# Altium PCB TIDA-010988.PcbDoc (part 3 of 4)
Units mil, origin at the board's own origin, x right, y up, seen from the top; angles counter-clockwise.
Board outline 3937.01 x 2559.06 mil, 4 copper layers (Top Layer, GND1, GND2, Bottom Layer), stack 61.6 mil thick; 270 components, 141 nets, 796 pads, 474 vias.
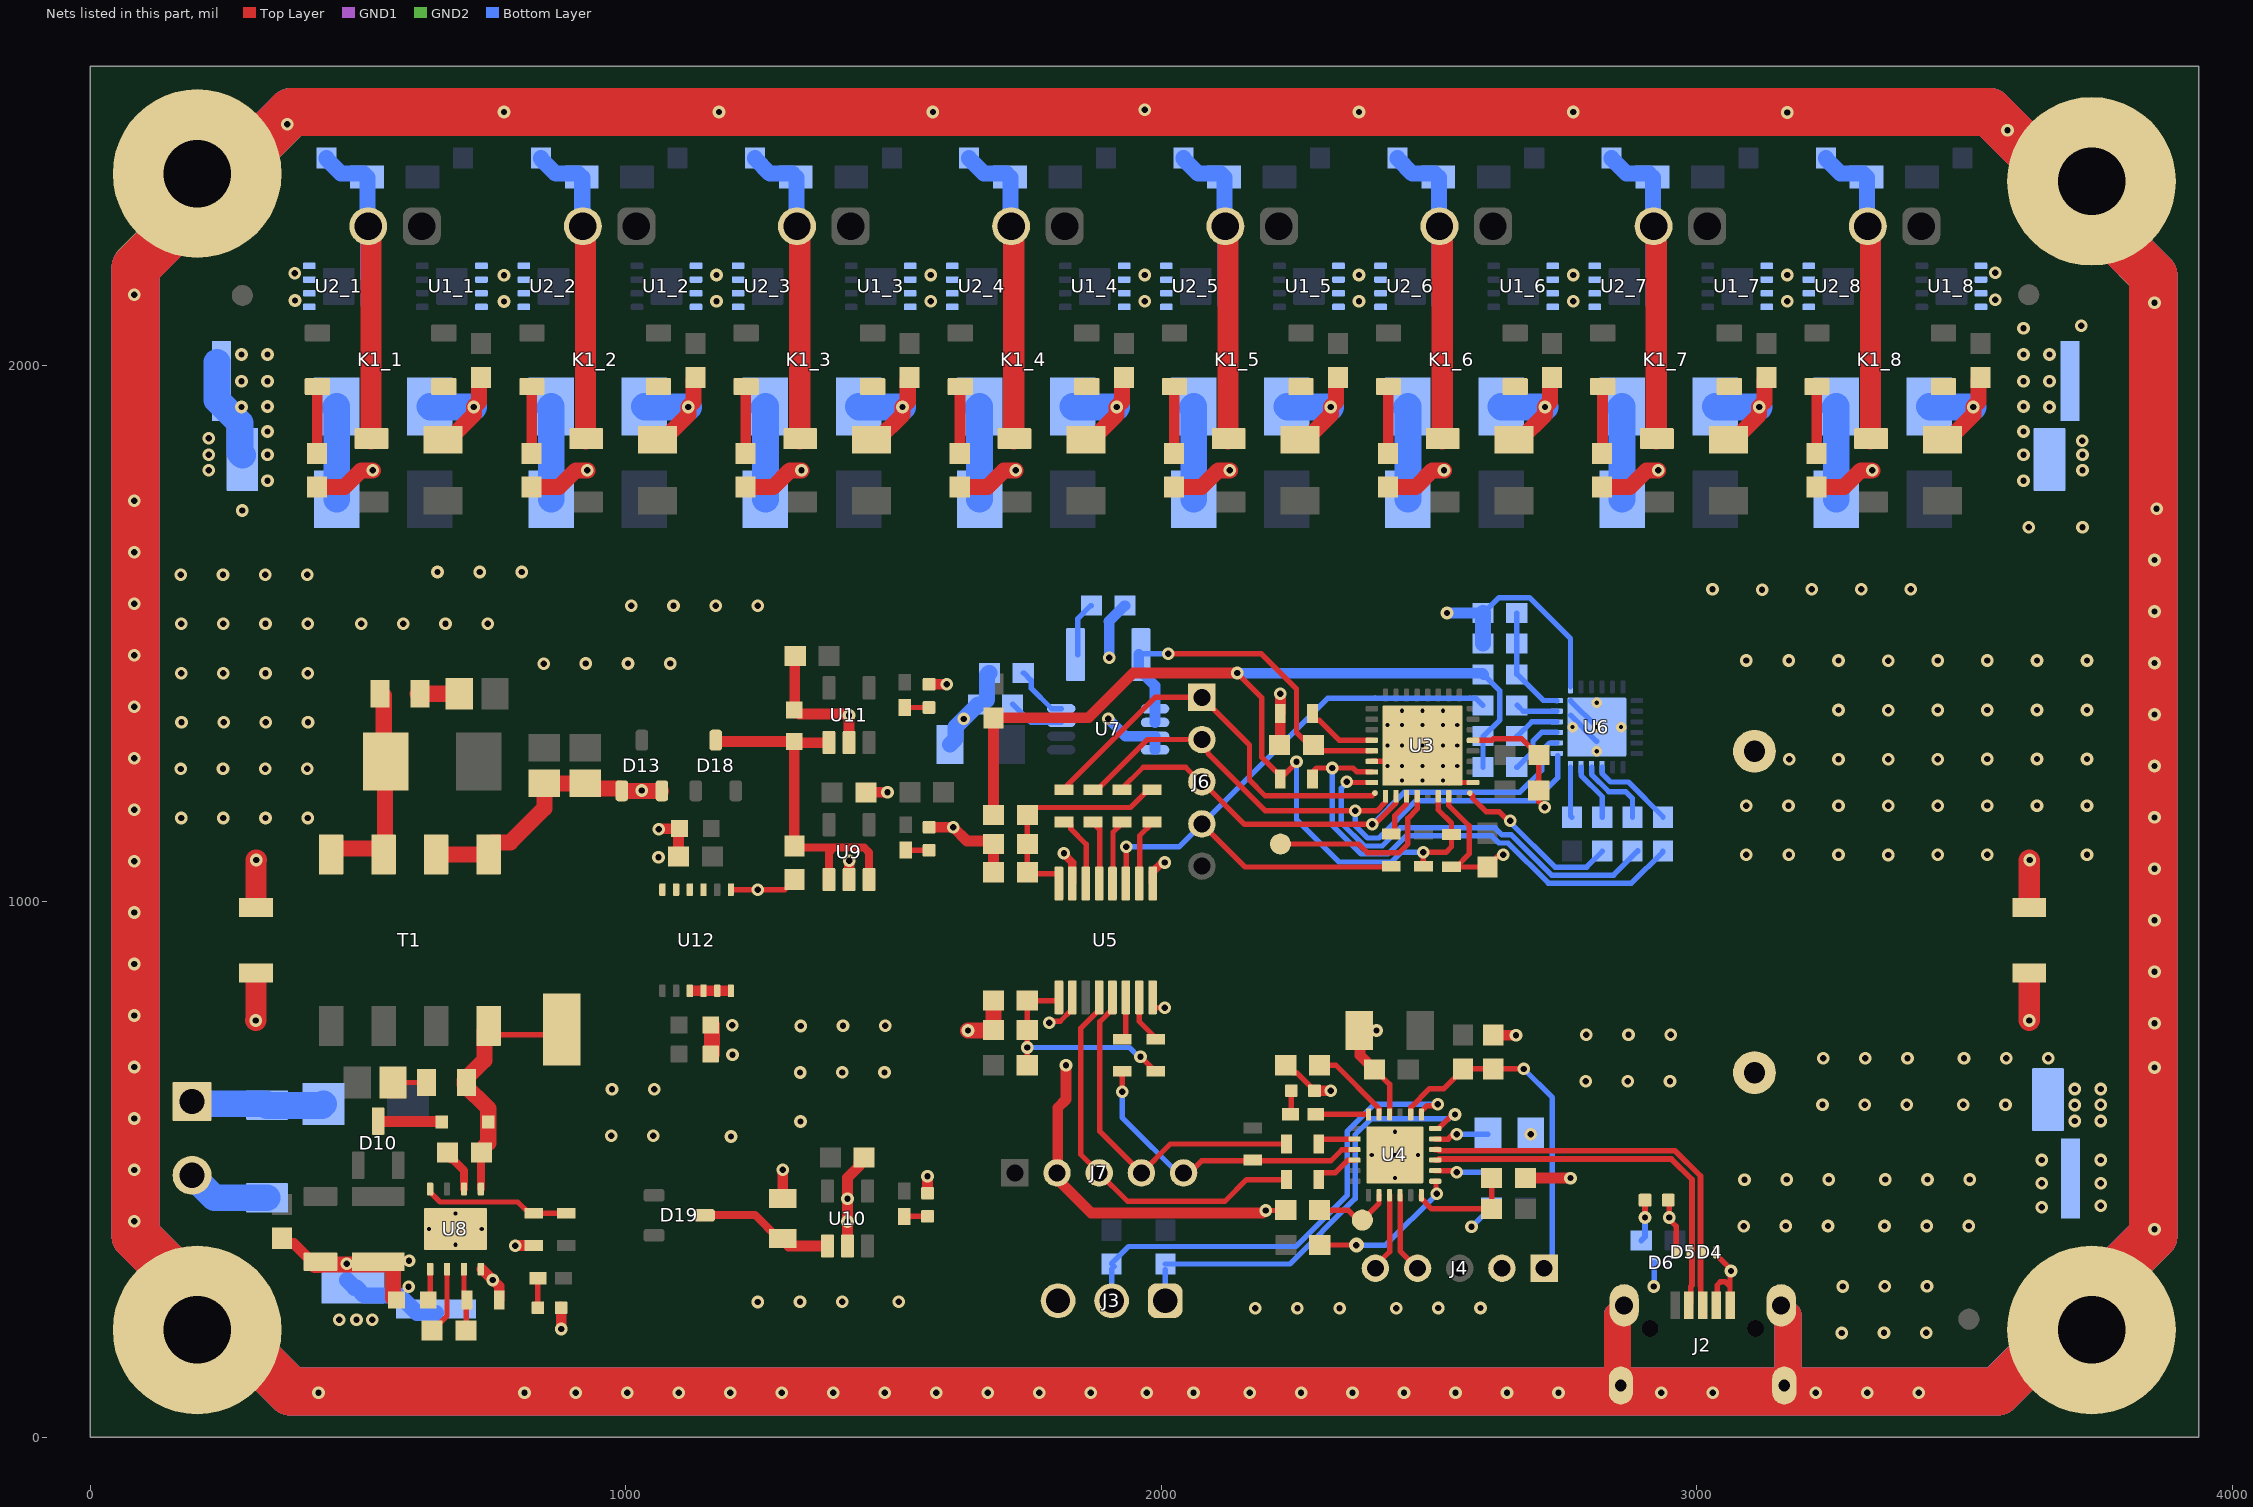
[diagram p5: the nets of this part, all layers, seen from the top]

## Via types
v1: diameter 23.62, hole 11.81, Top Layer to Bottom Layer, tented both sides, 374 vias
v2: diameter 19.68, hole 7.87, Top Layer to Bottom Layer, tented top, 64 vias
v3: diameter 19.68, hole 7.87, Top Layer to Bottom Layer, tented both sides, 26 vias
v4: diameter 19.68, hole 7.87, Top Layer to Bottom Layer, 9 vias
v5: diameter 28, hole 12, Top Layer to Bottom Layer, tented both sides, 1 vias

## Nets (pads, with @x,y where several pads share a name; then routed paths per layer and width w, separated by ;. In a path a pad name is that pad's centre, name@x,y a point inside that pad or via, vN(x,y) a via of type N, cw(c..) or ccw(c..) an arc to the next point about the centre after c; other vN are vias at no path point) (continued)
E_GND: C1_1.2 C1_2.2 C1_3.2 C1_4.2 C1_5.2 C1_6.2 C1_7.2 C1_8.2 C2_1.1 C2_2.1 C2_3.1 C2_4.1 C2_5.1 C2_6.1 C2_7.1 C2_8.1 C24.1 C25.2 C45.1 C46.2 H1.1 H2.1 H3.1 H4.1 J2.Z1 J2.Z2 J2.Z3 J2.Z4 R1_1.1 R1_2.1 R1_3.1 R1_4.1 R1_5.1 R1_6.1 R1_7.1 R1_8.1 R2_1.2 R2_2.2 R2_3.2 R2_4.2 R2_5.2 R2_6.2 R2_7.2 R2_8.2 R36.2 R37.2 R39.2 R40.2 | length 47388
  Top Layer w50: J2.Z4@2851.63,110.96 J2.Z1@2851.63,227.74 ; J2.Z3@3169.98,110.96 J2.Z2@3169.98,227.74
  Top Layer w90: H3.1@260.87,200 H3.1@259.08,200 ; 374.07,2473.16 374.98,2473.16 ; v1@2739.82,85 2164.98,85 1972.77,85 1483.71,85 1003.18,85 810.97,85 374.08,85 H3.1@259.08,200 ; v1@2741.61,85 2858.25,85 3222.14,85 3561.36,85 3676.36,200 H4.1@3737.01,200 3737.01,260.87 3852.01,375.87 ; v1@3852.01,388.04 3852.01,964.67 3852.01,1060.78 3852.01,1252.99 3852.01,1349.09 3852.01,1733.51 3852.01,2117.94 3852.01,2163.11 ; 3852.01,2168.61 3737.01,2283.61 H2.1@3737.01,2344.49 3676.13,2344.49 3546.57,2474.06 v1(2769.12,2474.06) v1(2369.26,2474.06) v1(1573.68,2474.06) v1(1174.17,2474.06) v1(772.81,2474.06) 375.87,2474.06 374.98,2473.16 ; H3.1@259.08,200 H3.1@200,200 200,260.87 85,375.87 85,594.82 85,690.92 85,1267.56 85,1651.98 85,2132.51 85,2183.18 200,2298.18 H1.1@200,2359.06 260.87,2359.06 374.98,2473.16
  GND1 w50: J2.Z4@2851.63,110.96 J2.Z1@2851.63,227.74 ; J2.Z3@3169.98,110.96 J2.Z2@3169.98,227.74
  GND1 w90: H3.1@200,260.87 85,375.87 85,402.61 85,690.92 85,979.24 85,1267.56 85,1651.98 85,2183.18 200,2298.18 H1.1@200,2359.06 ; H1.1@259.07,2358.16 374.07,2473.16 ; H3.1@259.08,200 374.08,85 ; 375.87,85 1003.18,85 1483.71,85 1972.77,85 2261.09,85 2357.19,85 2858.25,85 3318.25,85 3561.13,85 H4.1@3676.13,200 ; 375.87,2474.06 v1(772.81,2474.06) v1(1174.17,2474.06) v1(1573.68,2474.06) v1(2369.26,2474.06) v1(2769.12,2474.06) 3546.57,2474.06 H2.1@3676.13,2344.49 ; H4.1@3735.2,259.98 3850.2,374.98 ; H2.1@3737.01,2283.61 3852.01,2168.61 3852.01,1829.62 3852.01,1733.51 3852.01,1541.31 3852.01,1252.99 3852.01,964.67 3852.01,690 3852.01,375.87
  GND2 w50: J2.Z4@2851.63,110.96 J2.Z1@2851.63,227.74 ; J2.Z3@3169.98,110.96 J2.Z2@3169.98,227.74
  GND2 w90: 85,2183.18 85,1651.98 85,1555.87 85,979.24 85,787.03 85,375.87 H3.1@200,260.87 ; 86.64,2187.45 H1.1@201.64,2302.45 ; H3.1@200,200 259.08,200 374.08,85 810.97,85 1003.18,85 1483.71,85 1675.92,85 2164.98,85 2645.51,85 3029.93,85 3169.98,85 3561.13,85 ; H1.1@200,2359.06 260.87,2359.06 375.87,2474.06 v1(772.81,2474.06) v1(1174.17,2474.06) v1(1573.68,2474.06) v1(2369.26,2474.06) v1(2769.12,2474.06) 3546.57,2474.06 H2.1@3676.13,2344.49 ; 3561.36,85 H4.1@3676.36,200 ; H4.1@3737.01,200 3737.01,260.87 3852.01,375.87 3852.01,690 3852.01,1349.09 3852.01,1541.31 3852.01,1637.41 3852.01,1733.51 3852.01,1829.62 3852.01,2168.13 3823.14,2197 3823.14,2197.48 3737.01,2283.61 H2.1@3737.01,2344.49
  Bottom Layer w50: J2.Z4@2858.25,96.28 2858.25,104.35 2851.63,110.96 2851.63,227.74 2864.15,240.26 J2.Z1@2864.15,245.88 ; J2.Z2@3157.46,245.88 3157.46,240.26 3169.98,227.74 3169.98,110.96 3163.36,104.35 J2.Z3@3163.36,96.28
  Bottom Layer w90: H3.1@260.87,200 H3.1@259.08,200 ; 374.08,85 H3.1@259.08,200 ; 375.87,85 426.55,85 1003.18,85 1483.71,85 1868.13,85 2645.51,85 2933.82,85 3163.36,85 3561.13,85 3676.13,200 H4.1@3737.01,200 3737.01,260.87 3852.01,375.87 3852.01,388.04 3852.01,482.36 3852.01,610.46 3852.01,676.36 3852.01,868.57 3852.01,1252.99 3852.01,1445.2 3852.01,1733.51 3852.01,1833.15 3852.01,2168.61 3737.01,2283.61 H2.1@3737.01,2344.49 3676.13,2344.49 3546.57,2474.06 3420.38,2474.06 3240.85,2474.06 3096.29,2474.06 v1(2769.12,2474.06) 2696.43,2474.06 2441.13,2474.06 v1(2369.26,2474.06) 1896.71,2474.06 1717.51,2474.06 v1(1573.68,2474.06) 1421.07,2474.06 v1(1174.17,2474.06) v1(772.81,2474.06) 517.16,2474.06 375.87,2474.06 260.87,2359.06 H1.1@200,2359.06 200,2298.18 85,2183.18 85,1833.15 85,1459.77 85,690.92 85,594.82 85,375.87 200,260.87 H3.1@200,200 H3.1@259.08,200
  other v1: 426.55,82.52 810.97,82.52 907.08,82.52 1003.18,82.52 1099.29,82.52 1195.39,82.52 1291.5,82.52 1387.61,82.52 1483.71,82.52 1579.82,82.52 1675.92,82.52 1772.03,82.52 1868.13,82.52 1972.77,82.52 2060.34,82.52 2164.98,82.52 2261.09,82.52 2357.19,82.52 2453.3,82.52 2549.4,82.52 2645.51,82.52 2741.61,82.52 2933.82,82.52 3029.93,82.52 3222.14,82.52 3318.25,82.52 3414.35,82.52 3854.49,388.04 82.52,402.61 82.52,498.71 82.52,594.82 82.52,690.92 3854.49,690 3854.49,772.46 82.52,787.03 3854.49,868.57 82.52,883.13 3854.49,964.67 82.52,979.24 3854.49,1060.78 82.52,1075.34 3854.49,1156.88 82.52,1171.45 3854.49,1252.99 82.52,1267.56 3854.49,1349.09 82.52,1363.66 3854.49,1445.2 82.52,1459.77 3854.49,1541.31 82.52,1555.87 3854.49,1637.41 82.52,1651.98 3858.42,1733.51 82.52,1748.08 3854.49,2117.94 82.52,2132.51 3580,2440 368.18,2450.9 3168.98,2473.16 1969.39,2478.33
F\A\U\L\T\: R9.2 U6.11 | length 110.1
  Bottom Layer w10: U6.11@2783.68,1250.78 2783.96,1250.51 2783.96,1235.47 2823.4,1196.02 R9.2@2823.4,1157.18
GND: C3.2 C4.2 C5.2 C6.2 C7.2 C8.2 C11.2 C12.2 C13.2 C14.2 C18.1 C20.2 C22.2 C23.2 C25.1 C28.2 C29.2 C30.2 C35.2 C36.2 C40.2 C43.1 C44.2 C46.1 D13.1 D13.2 D17.1 D21.1 R3_1.1 R3_2.1 R3_3.1 R3_4.1 R3_5.1 R3_6.1 R3_7.1 R3_8.1 R33.1 R35.1 R37.1 R40.1 T1.7 T1.8 TP1.1 U1_1.5 U1_1.6 U1_1.7 U1_1.8 U1_2.5 U1_2.6 U1_2.7 U1_2.8 U1_3.5 U1_3.6 U1_3.7 U1_3.8 U1_4.5 U1_4.6 U1_4.7 U1_4.8 U1_5.5 U1_5.6 U1_5.7 U1_5.8 U1_6.5 U1_6.6 U1_6.7 U1_6.8 U1_7.5 U1_7.6 U1_7.7 U1_7.8 U1_8.5 U1_8.6 U1_8.7 U1_8.8 U2_1.5 U2_1.6 U2_1.7 U2_1.8 U2_2.5 U2_2.6 U2_2.7 U2_2.8 U2_3.5 U2_3.6 U2_3.7 U2_3.8 U2_4.5 U2_4.6 U2_4.7 U2_4.8 U2_5.5 U2_5.6 U2_5.7 U2_5.8 U2_6.5 U2_6.6 U2_6.7 U2_6.8 U2_7.5 U2_7.6 U2_7.7 U2_7.8 U2_8.5 U2_8.6 U2_8.7 U2_8.8 U3.15 U3.25 U3.28 U3.32 U3.37 U5.9 U5.15 U6.19 U6.25 U7.7 U7.8 U9.2 U11.2 U12.7 U12.9 U12.10 U12.11 U12.12 | length 4400.4
  Top Layer w10: U12.7@1196.56,1022.04 1297.12,1022.04 C35.2@1314.86,1039.77 ; U3.15@2393.15,1261.5 2417.83,1261.5 2422.68,1256.66 v3(2422.68,1252.64) ; U3.37@2497.48,1300.87 v3(2487.64,1291.03) v3(2526.02,1252.64) 2556.46,1222.21 2582.05,1222.21 U3.28@2582.13,1222.13 ; v3(2526.02,1226.07) 2532.01,1226.07 U3.37@2536.85,1221.23 ; U3.25@2536.85,1196.54 2536.85,1179.31 2574.9,1141.27 2574.9,1088.51 2551.7,1065.31 2551.7,1064.33 C4.2@2609.12,1064.33 2609.12,1065.31 2628.58,1084.78 2636.05,1084.78 v1(2638.66,1087.38) ; U3.32@2582.13,1300.87 2617.26,1300.87 2619.9,1303.52 2673.56,1303.52 2704,1273.08 C8.2@2704.98,1273.08 2704.98,1207.19 C3.2@2704.92,1207.13 2704.92,1186.28 2705.42,1186.28 v1(2716.04,1175.65)
  Top Layer w15: v1@1818.27,1088.52 1833.82,1072.97 1833.82,1034.55 U5.15@1833.96,1034.41 ; U5.9@1983.96,1034.41 1983.96,1054.88 2001.85,1072.77 v1(2006.7,1072.77)
  Top Layer w20: v1(1061.93,1134.98) 1062.55,1135.6 1098.14,1135.6 1098.76,1136.23 C44.2@1098.76,1083.52 ; C40.2@1315.74,1457.11 1315.74,1360.42 1314.86,1359.54 1314.86,1358.74 1323.56,1350.04 1413.85,1350.04 1416.08,1347.81 v1(1417.06,1347.81) ; U11.2@1417.01,1296.55 v1@1417.01,1346.54 ; U9.2@1417.43,1041.17 v1@1417.43,1075.78 ; C36.2@1448.51,1203.81 v1@1488.95,1203.78 ; D17.1@1566.44,1138.59 v1@1611.44,1138.59 ; D21.1@1566.44,1405.35 1566.82,1405.73 v1@1596.69,1405.73 ; v1(1611.47,1138.56) 1637.29,1112.73 1681.46,1112.73 C12.2@1686.98,1107.22 C11.2@1686.98,1054.5 ; C5.2@2222.41,1291.69 C5.2@2222.41,1305.03 ; C5.2@2222.43,1305.05 C6.2@2222.41,1350.91 ; C6.2@2222.62,1351.12 v1@2222.62,1385.95
  Top Layer w30: R3_1.1@423.44,1773.52 474.86,1773.52 506.35,1805.02 v1(527.74,1805.02) ; T1.7@646.25,1087.59 T1.8@744.29,1087.59 ; T1.8@744.29,1102.15 752.32,1110.19 784.78,1110.19 848.15,1173.56 C28.2@848.15,1220.34 C29.2@924.62,1220.34 933.72,1211.25 989.62,1211.25 992.81,1208.06 D13.1@992.81,1206.56 D13.2@1066.12,1206.56 ; R3_2.1@824.06,1773.52 875.47,1773.52 906.97,1805.02 v1(928.36,1805.02) ; R3_3.1@1223.92,1773.52 1275.34,1773.52 1306.83,1805.02 v1(1328.22,1805.02) ; C40.2@1315.74,1457.11 C40.2@1316.62,1457.99 ; R3_4.1@1623.79,1773.52 1675.2,1773.52 1706.69,1805.02 v1(1728.09,1805.02) ; R3_5.1@2023.65,1773.52 2075.06,1773.52 2106.55,1805.02 v1(2127.95,1805.02) ; R3_6.1@2423.51,1773.52 2474.92,1773.52 2506.42,1805.02 v1(2527.81,1805.02) ; R3_7.1@2823.37,1773.52 2874.78,1773.52 2906.28,1805.02 v1(2927.67,1805.02) ; R3_8.1@3223.23,1773.52 3274.64,1773.52 3306.14,1805.02 v1(3327.53,1805.02)
  Top Layer w40: C20.2@309.72,994.48 309.72,1076.86 v1(310.18,1077.32) ; C30.2@3620.87,994.48 v1@3620.87,1076.86
  GND2 w10: v1@2716.04,1175.16 v1(2716.04,1175.65)
  Bottom Layer w10: C13.2@2600.84,1538.44 2601.82,1538.44 2630.52,1567.14 2687.66,1567.14 2764,1490.79 U6.19@2764,1400.39 ; v1(2638.66,1087.38) v1@2641.26,1084.78 ; U6.25@2764.08,1347.94 U6.25@2813.02,1299 ; U6.25@2764.27,1374.52 v3(2813.21,1325.59)
  Bottom Layer w20: v1(1900.9,1341.08) 1933.38,1308.6 U7.7@1988.5,1308.6 U7.8@1988.5,1283.01 ; v1(1902.99,1454.8) 1902.99,1521.87 1902.03,1522.83 1931.41,1552.21 R35.1@1932.4,1552.21 ; v1(2533.42,1538.44) C13.2@2600.84,1538.44
  Bottom Layer w30: C22.2@1605.6,1293.28 1616.19,1303.87 1616.19,1325.97 1658.28,1368.05 R33.1@1659.26,1368.05 ; R33.1@1674.68,1376.61 1674.68,1422.87 1678.39,1426.58 C23.2@1679.37,1426.58 ; C14.2@2600.84,1481.39 C13.2@2600.84,1538.44
  Bottom Layer w50: C25.1@237.09,2006.91 237.09,1936.04 279.8,1893.33 279.8,1837.68 R40.1@284.33,1833.15
  other v1: 1246.84,1022.04 1417.2,1076 3621.33,1077.32 1061.19,1082.8 3357.18,1086.77 3092.48,1087.17 3171.93,1087.27 3264.56,1087.27 3449.81,1087.27 3542.43,1087.36 3728.39,1087.36 1818.27,1090.21 170,1155.81 248.74,1155.9 327.48,1155.9 406.22,1155.9 3092.48,1178.8 3171.22,1178.89 3264.56,1178.89 3357.18,1178.39 3449.81,1178.89 3542.43,1178.98 3635.06,1178.98 3728.39,1178.98 1488.98,1203.75 1030.11,1207.24 169.29,1247.43 248.03,1247.52 326.77,1247.52 405.51,1247.52 3172.64,1265.73 3264.56,1265.73 3357.18,1265.23 3449.81,1265.73 3542.43,1265.83 3635.06,1265.83 3728.39,1265.83 170.71,1334.27 249.45,1334.37 328.19,1334.37 406.93,1334.37 1631.01,1340.79 3357.18,1356.85 3264.56,1357.35 3449.81,1357.35 3542.43,1357.45 3635.06,1357.45 3728.39,1357.45 2222.11,1388.08 1599.8,1405.78 170,1425.89 248.74,1425.99 327.48,1425.99 406.22,1425.99 846.95,1444.07 925.69,1444.17 1004.43,1444.17 1083.17,1444.17 3092.48,1449.75 3171.93,1449.84 3264.56,1449.84 3357.18,1449.34 3449.81,1449.84 3542.43,1449.94 3635.06,1449.94 3728.39,1449.94 170,1518.38 248.74,1518.47 327.48,1518.47 406.22,1518.47 506.1,1518.47 584.84,1518.57 663.58,1518.57 742.32,1518.57 1010.53,1552.21 1089.27,1552.3 1168.01,1552.3 1246.75,1552.3 3029.21,1582.67 3121.83,1582.17 3214.46,1582.67 3307.08,1582.76 3399.71,1582.76 169.29,1610 248.03,1610.09 326.77,1610.09 405.51,1610.09 648.7,1615.1 727.44,1615.1 806.18,1615.1 3620,1698.82 3720,1698.82 284.33,1730 331.29,1785.76 3610,1785.76 221.29,1805.02 3720,1805.02 221.29,1834.27 331.29,1834.27 3610,1834.27 3720,1834.27 3719.74,1860.19 221.29,1865 331.29,1877.52 3610,1877.52 282.83,1923.29 3658.46,1923.29 331.29,1924.23 3610,1924.23 282.83,1971.48 331.29,1971.48 3610,1971.48 3658.46,1971.48 282.83,2021.14 331.29,2021.14 3610,2021.14 3658.46,2021.14 3610,2070.08 3717.55,2074.8 772.81,2120.08 1169.67,2120.38 1569.53,2120.38 1969.39,2120.38 2369.26,2120.38 2769.12,2120.38 3168.98,2120.38 382.53,2121.9 3557.48,2123.71 772.81,2169.29 1169.67,2169.6 1569.53,2169.6 1969.39,2169.6 2369.26,2169.6 2769.12,2169.6 3168.98,2169.6 382.08,2172.93 3557.48,2173.85
  other v3: 2449.25,1226.07 2487.64,1226.07 2449.25,1252.64 2487.64,1252.64 2552.6,1252.64 2813.21,1280.31 2422.68,1291.03 2449.25,1291.03 2526.02,1291.03 2552.6,1291.03 2767.94,1325.59 2858.49,1325.59 2422.68,1329.42 2449.25,1329.42 2487.64,1329.42 2526.02,1329.42 2552.6,1329.42 2449.25,1355.99 2487.64,1355.99 2526.02,1355.99 2813.21,1370.86
GND_0V: C9.2 C10.2 C15.2 C16.1 C17.1 C19.1 C20.1 C24.2 C30.1 C31.1 C32.1 C33.2 C34.1 C37.1 C38.2 C39.2 C41.1 C42.1 C45.2 D3.1 D4.1 D5.1 D6.1 D7.1 D15.1 D16.2 D20.1 J2.4 J2.5 J3.3 J4.2 J5.2 J7.2 R11.1 R16.1 R24.2 R36.1 R39.1 R50.1 R52.1 TP2.1 U4.4 U4.25 U5.2 U5.8 U8.8 U8.9@682.27,388.27 U10.2 U12.3 U12.4 U12.5 U12.6 | length 3074.4
  Top Layer w10: v1(1790.96,773.7) 1793.56,776.31 1811.37,776.31 1832.22,797.16 1832.22,818.1 U5.2@1833.96,819.84 ; U5.8@1983.96,819.84 1983.96,803.94 1986.61,801.29 v1(2006.7,801.29) ; v1(2195.13,422.91) 2231.69,422.91 R16.1@2232.43,423.65 ; R24.2@2232.43,694.17 2246.13,680.47 2252.23,680.47 D7.1@2286.08,646.62 ; C16.1@2398.14,685.94 2399.12,685.94 2426.47,658.6 U4.4@2426.47,602.07 ; D3.1@2946.64,442.42 2948.51,440.56 v1(2948.51,410) 2948.51,406.31 2961.55,393.27 D5.1@2961.55,344.98 ; J2.4@3036.4,245.88 3038.13,247.61 3038.13,283.79 3043.99,289.65 3053.48,289.65 3061.99,281.14 ; D4.1@3036.83,344.98 3036.83,340.06 3063.78,313.1 v1(3063.78,310) 3061.99,308.21 3061.99,281.14 ; J2.5@3061.99,245.88 3061.99,281.14
  Top Layer w20: C33.2@358,371.07 358,370.09 366.7,361.39 380.19,361.39 C31.1@420.24,321.34 ; U8.8@731.8,313.46 763.92,281.34 R52.1@763.92,255.9 ; v1@793.69,357.56 R50.1@828.26,357.56 ; D15.1@877.61,243.15 D15.1@879.43,241.34 879.94,240.83 v1@879.94,202.4 ; U12.3@1124.21,833.06 U12.4@1145.38,833.06 U12.5@1170.97,833.06 U12.6@1192.42,833.06 ; C37.1@1293.38,448 1293.38,495.91 1295.31,497.84 v1@1295.31,498.82 ; v1@1414.08,445.22 1414.08,483.89 1435.51,505.32 1435.51,512.97 1444.21,521.67 C38.2@1445.19,521.67 ; U10.2@1414.24,356.82 v1(1414.24,402.3) v1(1414.24,445.06) ; v1(1563.49,487.06) 1563.58,486.97 1563.58,455.33 D20.1@1563.67,455.24 D20.1@1565.48,457.05 ; v1(1822.29,693.99) 1822.29,630.28 1806.69,614.68 1806.69,480.66 1869.09,418.26 2189.51,418.26 2194.15,422.91 v1(2195.13,422.91) ; D7.1@2286.08,646.62 v1(2316.46,646.62) ; C16.1@2398.14,685.94 2397.15,685.94 2388.45,694.64 2388.45,695.63 2371.19,712.89 2371.19,747.33 2359.54,758.98 v1(2402.01,758.98) ; C15.2@2619.89,750.28 v1(2662.37,750.28) ; R11.1@2679.84,483.47 v1(2764.23,483.47)
  Top Layer w30: C31.1@420.24,321.34 430.09,321.34 431.07,322.32 560.1,322.32 565.77,316.65 565.77,259.6 569.47,255.9 C34.1@570.45,255.9 ; C42.1@1160.8,715.09 C41.1@1160.8,769.55 ; v1(1639.26,758.98) 1686.03,758.98 C9.2@1686.76,759.71 C10.2@1686.76,814.71
  Top Layer w40: v1(309.26,777.77) 309.72,778.23 C20.1@309.72,860.62 ; v1@3620.87,778.23 C30.1@3620.87,860.62
  Bottom Layer w10: v1@2579.37,391.66 v1(2579.37,392.31) 2615.87,428.8 C39.2@2616.85,428.8 ; v1(2919.75,281.14) 2920.25,281.64 2920.25,325.06 D6.1@2920.74,325.55
  Bottom Layer w30: R39.1@479.52,293.27 494.04,278.74 497.45,278.74 511.98,264.21 577.75,264.21 610.47,231.5 C24.2@645.9,231.5
  Bottom Layer w50: J5.2@190.47,488.64 232.48,446.63 D16.2@330.54,446.63
  other v1: 3270.86,194.3 3349.6,194.39 3428.34,194.39 879.95,201.7 465.2,218.98 497.45,218.98 526.96,218.98 2175.5,240.57 2254.24,240.67 2332.98,240.67 2438.48,240.67 2517.22,240.76 2595.96,240.76 1246.67,252.19 1325.41,252.29 1404.15,252.29 1509.65,252.29 594.67,280.52 3272.27,281.14 3351.01,281.24 3429.75,281.24 752.09,293.27 479.34,323.36 595.61,328.98 793.95,357.3 3087.48,393.81 3166.22,393.91 3244.96,393.91 3350.46,393.91 3429.2,394 3507.94,394 3643.95,428.8 3753.95,431.95 3643.95,473.95 3753.95,473.95 3088.9,480.66 3167.64,480.75 3246.38,480.75 3351.88,480.75 3430.62,480.84 3509.36,480.84 1293.37,499.27 3643.95,517.2 3753.95,517.2 1196.7,561.23 972.95,562.51 1051.69,562.61 2690.04,565.5 1326.36,589.04 3705.49,590 3753.95,590 3705.49,619.82 3234.51,620.1 3313.25,620.19 3391.99,620.19 3497.49,620.19 3576.23,620.29 3753.95,620.29 974.37,649.36 1053.11,649.45 3705.49,649.77 3753.95,649.77 2792.37,664.17 2871.11,664.27 2949.85,664.27 1325.66,680.66 1404.4,680.76 1483.14,680.76 3235.92,706.94 3314.66,707.03 3393.4,707.03 3498.9,707.03 3577.64,707.13 3656.38,707.13 1199.33,713.63 2793.79,751.02 2872.53,751.11 2951.27,751.11 1327.07,767.51 1405.81,767.6 1484.55,767.6 1198.73,769.05 3620.41,777.77
  other v4: 682.27,359.13 633.06,388.27 731.49,388.27 682.27,417.4 2436.31,483.47 2393,526.78 2436.31,526.78 2479.62,526.78 2436.31,570.08
IOVDD: C7.1 L2.2 L3.1 L4.1 R10.1 R27.2 R28.2 R56.1 U3.24 | length 2185.7
  Top Layer w10: v1(2141.6,1426.57) 2187.53,1380.64 2187.53,1269.32 2219.93,1236.92 R10.1@2220.92,1236.92 ; R10.1@2220.96,1228.47 2221.94,1228.47 2252.59,1259.13 v1(2252.59,1260.53) ; R56.1@2482.36,1065.82 R56.1@2489.86,1065.82 2489.33,1066.35 v1(2489.33,1091.58) 2531.32,1091.58 2541.89,1102.15 2541.89,1119.99 2541.18,1120.7 2537.6,1120.7 C7.1@2541.89,1124.99 2541.89,1146.07 2517.24,1170.71 2517.24,1196.46 U3.24@2517.17,1196.54
  Top Layer w20: L4.1@1686.73,1342.74 1864.14,1342.74 1947.97,1426.57 v1(2141.6,1426.57) ; L4.1@1686.86,1342.62 1686.86,1161.73 L2.2@1686.98,1161.6
  Top Layer w30: L4.1@1686.73,1342.74 L4.1@1686.86,1342.62
  Bottom Layer w10: v1(2252.59,1260.53) 2252.59,1152.69 2331.73,1073.55 2429.6,1073.55 2447.63,1091.58 v1(2489.33,1091.58) ; R28.2@2600.84,1250.85 R27.2@2600.84,1308.5 2601.82,1308.5 2632.33,1339.02 2632.33,1393.28 L3.1@2601.82,1423.79
  Bottom Layer w20: v1(2141.6,1426.57) 2142.3,1425.88 2599.73,1425.88 L3.1@2601.82,1423.79
"iso C\S\_ADC": J6.1 R15.2 U3.18 | length 769
  Top Layer w10: R15.2@1818.27,1209.8 1818.27,1210.79 1988.5,1381.01 J6.1@2075.9,1381.01 2164.76,1292.16 2164.76,1226.43 2193.84,1197.35 2393.79,1197.35 2398.88,1202.45 U3.18@2399.06,1202.45
"iso SCLK": J6.2 R17.2 U3.19 U6.13 | length 1169.5
  Top Layer w10: R17.2@1872.8,1208.31 1880.3,1208.31 1974.27,1302.27 J6.2@2075.9,1302.27 2075.9,1291.13 2087.34,1279.69 2087.34,1276.31 2194.44,1169.21 v1(2361.97,1169.21) 2402.52,1169.21 2418.66,1185.35 2418.66,1196.46 U3.19@2418.74,1196.54
  Bottom Layer w10: v1(2361.97,1169.21) 2361.97,1141.92 2385.33,1118.55 2406.46,1118.55 2475.98,1188.08 2697.62,1188.08 2740.19,1230.65 U6.13@2740.19,1272.19
"iso SDI": J6.3 R18.2 U3.20 U6.14 | length 1035.5
  Top Layer w10: R18.2@1923.5,1207.69 1966.34,1250.53 2045.5,1250.53 2072.5,1223.53 J6.3@2075.9,1223.53 2155.38,1144.05 v1(2394.14,1144.05) 2395.7,1142.49 2397.01,1142.49 2438.35,1183.83 U3.20@2438.35,1196.46
  Bottom Layer w10: v1(2394.14,1144.05) 2454.22,1204.14 2669.64,1204.14 2710.49,1244.98 2710.49,1281.05 2725.23,1295.78 2738.13,1295.78 U6.14@2738.41,1296.06
"iso SDO": J6.4 R5.1 R12.2 U5.11 | length 1238.9
  Top Layer w10: v1(1934.44,1101.96) 1934.92,1101.48 1934.92,1051.92 U5.11@1935.69,1052.69 ; J6.4@2080.91,1149.8 J6.4@2075.9,1144.79 2156.41,1064.29 R12.2@2436.31,1064.29
  Bottom Layer w10: v1(1934.44,1101.96) 2033.07,1101.96 J6.4@2075.9,1144.79 2310.43,1379.32 2587.73,1379.32 R5.1@2600.84,1366.22
NetC2_1_2: C2_1.2 F1_1.1 J1_1.2 R2_1.1 U2_1.1 U2_1.2 U2_1.3 U2_1.4 | length 825.1
  Top Layer w40: J1_1.2@519.41,2260.7 524.44,2255.68 F1_1.1@524.44,1863.71
  Bottom Layer w30: R2_1.1@441.07,2387.91 441.07,2386.93 468.86,2359.13 510.51,2359.13 C2_1.2@517.16,2352.48 518.29,2351.35 518.29,2261.83 J1_1.2@519.41,2260.7 ; U2_1.2@519.41,2165.34 J1_1.2@519.41,2260.7 ; U2_1.4@519.65,2114.16 519.65,2139.75 519.65,2165.34 519.65,2190.93 519.65,2260.47 J1_1.2@519.41,2260.7
NetC2_2_2: C2_2.2 F1_2.1 J1_2.2 R2_2.1 U2_2.1 U2_2.2 U2_2.3 U2_2.4 | length 825.1
  Top Layer w40: J1_2.2@920.03,2260.7 925.05,2255.68 F1_2.1@925.05,1863.71
  Bottom Layer w30: R2_2.1@841.68,2387.91 841.68,2386.92 869.48,2359.13 911.13,2359.13 C2_2.2@917.78,2352.48 918.91,2351.35 918.91,2261.83 J1_2.2@920.03,2260.7 ; U2_2.2@920.03,2165.34 J1_2.2@920.03,2260.7 ; U2_2.4@920.27,2114.16 920.27,2139.75 920.27,2165.34 920.27,2190.93 920.27,2260.47 J1_2.2@920.03,2260.7
NetC2_3_2: C2_3.2 F1_3.1 J1_3.2 R2_3.1 U2_3.1 U2_3.2 U2_3.3 U2_3.4 | length 825.1
  Top Layer w40: J1_3.2@1319.89,2260.7 1324.92,2255.68 F1_3.1@1324.92,1863.71
  Bottom Layer w30: R2_3.1@1241.54,2387.91 1241.54,2386.92 1269.34,2359.13 1310.99,2359.13 C2_3.2@1317.64,2352.48 1318.77,2351.35 1318.77,2261.83 J1_3.2@1319.89,2260.7 ; U2_3.2@1319.89,2165.34 J1_3.2@1319.89,2260.7 ; U2_3.4@1320.13,2114.16 1320.13,2139.75 1320.13,2165.34 1320.13,2190.93 1320.13,2260.47 J1_3.2@1319.89,2260.7
NetC2_4_2: C2_4.2 F1_4.1 J1_4.2 R2_4.1 U2_4.1 U2_4.2 U2_4.3 U2_4.4 | length 825.1
  Top Layer w40: J1_4.2@1719.75,2260.7 1724.78,2255.68 F1_4.1@1724.78,1863.71
  Bottom Layer w30: R2_4.1@1641.41,2387.91 1641.41,2386.92 1669.2,2359.13 1710.85,2359.13 C2_4.2@1717.51,2352.48 1718.63,2351.35 1718.63,2261.83 J1_4.2@1719.75,2260.7 ; U2_4.2@1719.75,2165.34 J1_4.2@1719.75,2260.7 ; U2_4.4@1719.99,2114.16 1719.99,2139.75 1719.99,2165.34 1719.99,2190.93 1719.99,2260.47 J1_4.2@1719.75,2260.7
NetC2_5_2: C2_5.2 F1_5.1 J1_5.2 R2_5.1 U2_5.1 U2_5.2 U2_5.3 U2_5.4 | length 825.1
  Top Layer w40: J1_5.2@2119.61,2260.7 2124.64,2255.68 F1_5.1@2124.64,1863.71
  Bottom Layer w30: R2_5.1@2041.27,2387.91 2041.27,2386.92 2069.06,2359.13 2110.71,2359.13 C2_5.2@2117.37,2352.48 2118.49,2351.35 2118.49,2261.83 J1_5.2@2119.61,2260.7 ; U2_5.2@2119.61,2165.34 J1_5.2@2119.61,2260.7 ; U2_5.4@2119.85,2114.16 2119.85,2139.75 2119.85,2165.34 2119.85,2190.93 2119.85,2260.47 J1_5.2@2119.61,2260.7
NetC2_6_2: C2_6.2 F1_6.1 J1_6.2 R2_6.1 U2_6.1 U2_6.2 U2_6.3 U2_6.4 | length 825.1
  Top Layer w40: J1_6.2@2519.48,2260.7 2524.5,2255.68 F1_6.1@2524.5,1863.71
  Bottom Layer w30: R2_6.1@2441.13,2387.91 2441.13,2386.92 2468.92,2359.13 2510.57,2359.13 C2_6.2@2517.23,2352.48 2518.35,2351.35 2518.35,2261.83 J1_6.2@2519.48,2260.7 ; U2_6.2@2519.48,2165.34 J1_6.2@2519.48,2260.7 ; U2_6.4@2519.71,2114.16 2519.71,2139.75 2519.71,2165.34 2519.71,2190.93 2519.71,2260.47 J1_6.2@2519.48,2260.7
NetC2_7_2: C2_7.2 F1_7.1 J1_7.2 R2_7.1 U2_7.1 U2_7.2 U2_7.3 U2_7.4 | length 825.1
  Top Layer w40: J1_7.2@2919.34,2260.7 2924.36,2255.68 F1_7.1@2924.36,1863.71
  Bottom Layer w30: R2_7.1@2840.99,2387.91 2840.99,2386.92 2868.79,2359.13 2910.44,2359.13 C2_7.2@2917.09,2352.48 2918.21,2351.35 2918.21,2261.83 J1_7.2@2919.34,2260.7 ; U2_7.2@2919.34,2165.34 J1_7.2@2919.34,2260.7 ; U2_7.4@2919.57,2114.16 2919.57,2139.75 2919.57,2165.34 2919.57,2190.93 2919.57,2260.47 J1_7.2@2919.34,2260.7
NetC2_8_2: C2_8.2 F1_8.1 J1_8.2 R2_8.1 U2_8.1 U2_8.2 U2_8.3 U2_8.4 | length 825.1
  Top Layer w40: J1_8.2@3319.2,2260.7 3324.22,2255.68 F1_8.1@3324.22,1863.71
  Bottom Layer w30: R2_8.1@3240.85,2387.91 3240.85,2386.92 3268.65,2359.13 3310.3,2359.13 C2_8.2@3316.95,2352.48 3318.07,2351.35 3318.07,2261.83 J1_8.2@3319.2,2260.7 ; U2_8.2@3319.2,2165.34 J1_8.2@3319.2,2260.7 ; U2_8.4@3319.43,2114.16 3319.43,2139.75 3319.43,2165.34 3319.43,2190.93 3319.43,2260.47 J1_8.2@3319.2,2260.7
NetC9_1: C9.1 C10.1 L1.2 R13.2 U5.1 | length 432.9
  Top Layer w10: L1.2@1749.75,704.22 C9.1@1749.75,759.71 C10.1@1749.75,814.71 1806.3,814.71 1808.96,817.37 U5.1@1808.96,819.84 ; v1(1961.21,709.88) 1962.2,709.88 1989.76,682.32 R13.2@1989.76,681.34
  Bottom Layer w10: v1(1749.71,727.2) 1940.62,727.2 1957.94,709.88 v1(1961.21,709.88)
NetC11_1: C11.1 C12.1 L2.1 R14.2 U5.16 | length 420.2
  Top Layer w10: U5.16@1809.92,1051.92 1752.56,1051.92 C11.1@1749.97,1054.5 C12.1@1749.97,1107.22 L2.1@1749.97,1161.6 1763.67,1175.3 1942.23,1175.3 1975.23,1208.31 R14.2@1982.73,1208.31
NetC13_1: C13.1 C14.1 L3.2 U6.18 | length 208.5
  Bottom Layer w10: L3.2@2663.83,1423.79 2664.81,1423.79 2713.52,1375.08 2738.13,1375.08 U6.18@2738.41,1374.8 ; L3.2@2663.83,1424.77 C14.1@2663.83,1481.39 C13.1@2663.83,1538.44
NetC18_2: C18.2 C35.1 D18.3 U9.1 U9.3 U11.1 | length 666
  Top Layer w15: C35.1@1314.86,1103.75 1318.29,1100.31 1388.58,1100.31 ; U9.1@1379.61,1040.75 1379.61,1091.34 1388.58,1100.31 ; U9.3@1453.17,1042 1454.41,1043.24 1454.41,1091.34 1445.44,1100.31 1388.58,1100.31
  Top Layer w20: D18.3@1168.16,1301.05 1168.16,1300.61 1169.97,1298.8 1312.61,1298.8 C18.2@1314.86,1296.55 ; C35.1@1314.86,1103.75 C18.2@1314.86,1296.55 ; U11.1@1379.61,1296.55 C18.2@1314.86,1296.55 ; U9.3@1453.17,1042 U9.3@1454.41,1040.75
NetC19_2: C19.2 U4.23 | length 102.2
  Top Layer w10: U4.23@2511.6,556.3 2535.74,556.3 2544.93,565.5 v1(2551.97,565.5)
  Bottom Layer w10: v1(2551.97,565.5) C19.2@2610.04,565.5
NetC21_1: C21.1 R35.2 | length 102.5
  Bottom Layer w10: C21.1@1843.81,1460.88 1843.81,1527.6 1868.42,1552.21 R35.2@1869.4,1552.21
NetC23_1: C23.1 U7.4 | length 107.1
  Bottom Layer w10: C23.1@1742.36,1426.58 1743.35,1426.58 1757.05,1412.87 1757.05,1398.32 1795.59,1359.79 U7.4@1813.3,1359.79
NetC26_1: C26.1 D11.2 T1.5 T1.6 | length 391.4
  Top Layer w30: T1.5@450.83,1098.46 548.87,1098.46 550.27,1099.87 550.27,1259.92 D11.2@551.68,1261.33 548.27,1264.75 548.27,1384.38 C26.1@544.85,1387.79
NetC26_2: C26.2 R42.1 | length 77.3
  Top Layer w30: C26.2@611.78,1387.79 R42.1@689.13,1387.79
NetC27_1: C27.1 D12.2 R48.2 T1.1 TP5.1 U8.1 | length 463
  Top Layer w10: T1.1@743.97,760.88 753.93,750.92 TP5.1@855.47,750.92
  Top Layer w15: U8.1@729.52,463.07 729.52,535.13 R48.2@736.33,541.94
  Top Layer w30: R48.2@736.33,541.94 743.42,549.03 D12.2@743.42,588.14 743.42,613.55 698.97,658.01 698.97,661.94 698.97,665.88 736.25,703.17 736.25,759.48 T1.1@744.29,767.51
NetC27_2: C27.2 R43.1 | length 66.5
  Top Layer w10: R43.1@565.57,661.85 631.95,661.85 C27.2@632.04,661.94
NetC34_2: C34.2 U8.5 | length 58.2
  Top Layer w10: C34.2@633.45,255.9 635.03,257.49 U8.5@635.03,313.46
NetC37_2: C37.2 D19.3 U10.1 | length 251
  Top Layer w15: D19.3@1148.83,414.86 1241.25,414.86 1285.51,370.6 C37.2@1293.38,370.6 ; C37.2@1293.38,368 C37.2@1304.56,356.82
  Top Layer w20: C37.2@1304.56,356.82 U10.1@1376.84,356.82
NetD1_1_1: D1_1.1 D2_1.1 | length 177
  Bottom Layer w50: D1_1.1@457.74,1921.54 D1_1.1@460.43,1924.23 D2_1.1@460.43,1751.06
NetD1_1_2: D1_1.2 K1_1.3 R0_1.1 R4_1.2 | length 234.7
  Top Layer w30: R4_1.2@658.8,1862.1 669.62,1862.1 716.45,1908.93 v1(716.45,1923.29) 726.17,1933.01 726.17,1974.9 R0_1.1@729.87,1978.6
  Bottom Layer w50: D1_1.2@634.44,1924.23 635.38,1923.29 v1(716.45,1923.29)
NetD1_2_1: D1_2.1 D2_2.1 | length 177
  Bottom Layer w50: D1_2.1@858.35,1921.54 D1_2.1@861.04,1924.23 D2_2.1@861.04,1751.05
NetD1_2_2: D1_2.2 K1_2.3 R0_2.1 R4_2.2 | length 234.7
  Top Layer w30: R4_2.2@1059.42,1862.1 1070.24,1862.1 1117.07,1908.93 v1(1117.07,1923.29) 1126.79,1933.01 1126.79,1974.9 R0_2.1@1130.49,1978.6
  Bottom Layer w50: D1_2.2@1035.06,1924.23 1036,1923.29 v1(1117.07,1923.29)
NetD1_3_1: D1_3.1 D2_3.1 | length 177
  Bottom Layer w50: D1_3.1@1258.22,1921.54 D1_3.1@1260.9,1924.22 D2_3.1@1260.9,1751.05
NetD1_3_2: D1_3.2 K1_3.3 R0_3.1 R4_3.2 | length 234.7
  Top Layer w30: R4_3.2@1459.28,1862.1 1470.1,1862.1 1516.93,1908.93 v1(1516.93,1923.29) 1526.65,1933.01 1526.65,1974.9 R0_3.1@1530.35,1978.6
  Bottom Layer w50: D1_3.2@1434.92,1924.22 1435.86,1923.29 v1(1516.93,1923.29)
NetD1_4_1: D1_4.1 D2_4.1 | length 177
  Bottom Layer w50: D1_4.1@1658.08,1921.54 D1_4.1@1660.76,1924.23 D2_4.1@1660.76,1751.05
NetD1_4_2: D1_4.2 K1_4.3 R0_4.1 R4_4.2 | length 234.7
  Top Layer w30: R4_4.2@1859.14,1862.1 1869.97,1862.1 1916.79,1908.93 v1(1916.79,1923.29) 1926.51,1933.01 1926.51,1974.9 R0_4.1@1930.21,1978.6
  Bottom Layer w50: D1_4.2@1834.78,1924.23 1835.72,1923.29 v1(1916.79,1923.29)
NetD1_5_1: D1_5.1 D2_5.1 | length 177
  Bottom Layer w50: D1_5.1@2057.94,1921.54 D1_5.1@2060.62,1924.22 D2_5.1@2060.62,1751.05
NetD1_5_2: D1_5.2 K1_5.3 R0_5.1 R4_5.2 | length 234.7
  Top Layer w30: R4_5.2@2259,1862.1 2269.83,1862.1 2316.65,1908.93 v1(2316.65,1923.29) 2326.37,1933.01 2326.37,1974.9 R0_5.1@2330.07,1978.6
  Bottom Layer w50: D1_5.2@2234.64,1924.22 2235.59,1923.29 v1(2316.65,1923.29)
NetD1_6_1: D1_6.1 D2_6.1 | length 177
  Bottom Layer w50: D1_6.1@2457.8,1921.54 D1_6.1@2460.48,1924.22 D2_6.1@2460.48,1751.05
NetD1_6_2: D1_6.2 K1_6.3 R0_6.1 R4_6.2 | length 234.7
  Top Layer w30: R4_6.2@2658.86,1862.1 2669.69,1862.1 2716.51,1908.93 v1(2716.51,1923.29) 2726.23,1933.01 2726.23,1974.9 R0_6.1@2729.93,1978.6
  Bottom Layer w50: D1_6.2@2634.5,1924.22 2635.45,1923.29 v1(2716.51,1923.29)
NetD1_7_1: D1_7.1 D2_7.1 | length 177
  Bottom Layer w50: D1_7.1@2857.66,1921.54 2860.35,1924.23 D2_7.1@2860.35,1751.06
NetD1_7_2: D1_7.2 K1_7.3 R0_7.1 R4_7.2 | length 234.7
  Top Layer w30: R4_7.2@3058.72,1862.1 3069.55,1862.1 3116.37,1908.93 v1(3116.37,1923.29) 3126.09,1933.01 3126.09,1974.9 R0_7.1@3129.79,1978.6
  Bottom Layer w50: D1_7.2@3034.36,1924.22 3035.31,1923.29 v1(3116.37,1923.29)
NetD1_8_1: D1_8.1 D2_8.1 | length 177
  Bottom Layer w50: D1_8.1@3257.52,1921.54 D1_8.1@3260.21,1924.22 D2_8.1@3260.21,1751.05
NetD1_8_2: D1_8.2 K1_8.3 R0_8.1 R4_8.2 | length 234.7
  Top Layer w30: R4_8.2@3458.58,1862.1 3469.41,1862.1 3516.23,1908.93 v1(3516.23,1923.29) 3525.95,1933.01 3525.95,1974.9 R0_8.1@3529.66,1978.6
  Bottom Layer w50: D1_8.2@3434.22,1924.22 3435.17,1923.29 v1(3516.23,1923.29)
NetD3_2: D3.2 R7.1 | length 78.4
  Top Layer w10.82: v1(2903.34,410) D3.2@2903.34,442.42
  Bottom Layer w10.82: R7.1@2896.26,366.91 2903.34,373.99 v1(2903.34,410)
NetD7_2: D7.2 R34.2 | length 44.6
  Top Layer w10: R34.2@2241.13,602.66 2242.78,604.3 D7.2@2242.78,646.62
NetD10_3: D10.3 D12.1 | length 127.7
  Top Layer w10: D10.3@538.17,597.15 D10.3@538.17,605.13
  Top Layer w20: D10.3@537.79,589.89 538.66,589.01 655.93,589.01 D12.1@656.81,588.14
NetD14_2: D14.2 D16.1 J5.1 | length 249.8
  Bottom Layer w50: J5.1@190.47,626.44 194.49,622.42 327.98,622.42 D16.1@330.54,619.86 ; J5.1@200,616.39 J5.1@200.26,616.65 ; D16.1@330.54,619.22 433.14,619.22 D14.2@435.97,622.04
NetD15_2: D15.2 R46.1 | length 55.6
  Top Layer w10: D15.2@836.12,241.34 836.12,296.38 R46.1@836.4,296.66
  Top Layer w20: D15.2@836.12,241.34 D15.2@836.26,241.48
NetD17_2: D17.2 R41.1 | length 44
  Top Layer w10: R41.1@1522.71,1095.87 1523.3,1095.28 D17.2@1566.44,1095.28
NetD20_2: D20.2 R54.2 | length 43.7
  Top Layer w10: R54.2@1519.93,411.93 D20.2@1563.67,411.93
NetD21_2: D21.2 R55.2 | length 45.3
  Top Layer w10: R55.2@1521.22,1362.13 1521.31,1362.04 D21.2@1566.44,1362.04
NetK1_1_2: K1_1.2 R3_1.2 | length 125.3
  Top Layer w20: R3_1.2@423.44,1836.51 423.92,1836.99 423.92,1960.91 K1_1.2@424.4,1961.39
NetK1_2_2: K1_2.2 R3_2.2 | length 125.3
  Top Layer w20: R3_2.2@824.06,1836.51 824.54,1836.99 824.54,1960.91 K1_2.2@825.02,1961.39
NetK1_3_2: K1_3.2 R3_3.2 | length 125.3
  Top Layer w20: R3_3.2@1223.92,1836.51 1224.4,1836.99 1224.4,1960.91 K1_3.2@1224.88,1961.39
NetK1_4_2: K1_4.2 R3_4.2 | length 125.3
  Top Layer w20: R3_4.2@1623.79,1836.51 1624.26,1836.99 1624.26,1960.91 K1_4.2@1624.74,1961.39
NetK1_5_2: K1_5.2 R3_5.2 | length 125.3
  Top Layer w20: R3_5.2@2023.65,1836.51 2024.13,1836.99 2024.13,1960.91 K1_5.2@2024.61,1961.39
NetK1_6_2: K1_6.2 R3_6.2 | length 125.3
  Top Layer w20: R3_6.2@2423.51,1836.51 2423.99,1836.99 2423.99,1960.91 K1_6.2@2424.47,1961.39
NetK1_7_2: K1_7.2 R3_7.2 | length 125.3
  Top Layer w20: R3_7.2@2823.37,1836.51 2823.85,1836.99 2823.85,1960.91 K1_7.2@2824.33,1961.39
NetK1_8_2: K1_8.2 R3_8.2 | length 125.3
  Top Layer w20: R3_8.2@3223.23,1836.51 3223.71,1836.99 3223.71,1960.91 K1_8.2@3224.19,1961.39
NetR5_2: R5.2 U6.17 | length 78.2
  Bottom Layer w10: R5.2@2664.81,1366.22 2675.91,1355.12 U6.17@2738.41,1355.12
NetR6_1: R6.1 U4.20 | length 111
  Top Layer w10: U4.20@2511.6,497.25 2511.88,496.97 2549.45,496.97 v1(2551.97,494.45)
  Bottom Layer w10: v1(2551.97,494.45) 2605.86,494.45 R6.1@2616.85,483.47
NetR8_1: R8.1 R11.2 U4.18 | length 203.1
  Top Layer w10: U4.18@2485.52,451.48 2485.52,445.34 2504.83,426.03 2587.18,426.03 2587.32,425.9 R8.1@2616.85,425.9 R11.2@2616.85,483.47
NetR9_1: R9.1 U3.27 | length 317.4
  Top Layer w10: U3.27@2576.22,1202.45 2576.22,1202.28 2581.33,1197.17 2581.33,1192.62 2606.31,1167.64 2630.97,1167.64 2647.72,1150.89 v1(2651.41,1150.89)
  Bottom Layer w10: v1@2652.59,1146.72 2735.21,1064.1 2794.3,1064.1 2823.4,1093.2 R9.1@2823.4,1094.18
NetR12_1: R12.1 U3.21 | length 78.3
  Top Layer w10: R12.1@2436.31,1127.28 2436.31,1160.57 2458.03,1182.3 2458.03,1196.46 U3.21@2458.11,1196.54
NetR13_1: R13.1 U5.7 | length 88.3
  Top Layer w10: U5.7@1958.96,819.84 1958.96,776.11 1989.76,745.31 R13.1@1989.76,744.33
NetR14_1: R14.1 U5.10 | length 104.3
  Top Layer w10: U5.10@1959.92,1051.92 1959.92,1123.01 1982.73,1145.83 R14.1@1982.73,1146.81
NetR15_1: R15.1 U5.14 | length 118
  Top Layer w10: R15.1@1818.27,1148.31 1825.77,1148.31 1830.77,1143.31 1830.77,1135.81 1859.92,1106.66 U5.14@1859.92,1051.92
NetR16_2: R16.2 TP3.1 U4.14 | length 147.3
  Top Layer w10: R16.2@2295.42,423.65 2348.76,423.65 2367.46,404.95 TP3.1@2375.41,404.95 2406.51,436.05 2406.51,451.2 U4.14@2406.78,451.48
NetR17_1: R17.1 U5.13 | length 99.9
  Top Layer w10: R17.1@1872.8,1146.81 1884.92,1134.69 U5.13@1884.92,1051.92
NetR18_1: R18.1 U5.12 | length 101.8
  Top Layer w10: U5.12@1909.92,1051.92 1909.92,1129.15 1926.6,1145.83 R18.1@1926.6,1146.81
NetR19_1: R19.1 U4.19 | length 310
  Top Layer w10: R19.1@2309.61,372.24 R19.1@2295.91,358.53 v5@2371.14,358.53 ; U4.19@2511.6,477.56 2512.81,477.56 2513.08,477.29 2513.08,455.48 v1(2514.56,454)
  Bottom Layer w10: v5(2364.32,358.17) 2418.73,358.17 v1(2514.56,454)
NetR20_2: R20.2 U5.6 | length 78.4
  Top Layer w10: R20.2@1926.98,744.33 1933.96,751.3 U5.6@1933.96,819.84
NetR21_1: R21.1 U4.10 | length 86.5
  Top Layer w10: R21.1@2293.93,480.66 2293.93,488.16 2298.93,493.16 2324.78,493.16 2348.55,516.93 U4.10@2361.01,516.93
NetR22_1: R22.1 U4.8 | length 73.3
  Top Layer w10: R22.1@2293.93,547.11 2293.93,551.3 2298.93,556.3 U4.8@2361.01,556.3
NetR24_1: R24.1 U4.5 | length 156.1
  Top Layer w10: R24.1@2295.42,694.17 2325.89,694.17 2406.78,613.28 U4.5@2406.78,602.07
NetR26_2: R26.2 U6.12 | length 94.7
  Bottom Layer w10: U6.12@2764,1250.78 2764,1159.84 R26.2@2766.66,1157.18
NetR27_1: R27.1 U6.16 | length 85.7
  Bottom Layer w10: R27.1@2663.83,1308.5 2664.81,1308.5 2691.74,1335.43 U6.16@2738.41,1335.43
NetR28_1: R28.1 U6.15 | length 113
  Bottom Layer w10: R28.1@2663.83,1250.85 2664.81,1250.85 2694.12,1280.15 2694.12,1299.81 2710.05,1315.74 U6.15@2738.41,1315.74
NetR29_1: R29.1 U6.9 | length 160.3
  Bottom Layer w10: U6.9@2823.05,1250.78 2823.33,1250.51 2823.33,1238.52 2838.84,1223.01 2872.1,1223.01 2936.95,1158.16 R29.1@2936.95,1157.18
NetR30_1: R30.1 U6.10 | length 143.8
  Bottom Layer w10: U6.10@2803.37,1250.78 2803.64,1250.51 2803.64,1236.99 2835.53,1205.11 2867.16,1205.11 2879.9,1192.37 R30.1@2879.9,1157.18
NetR33_2: R33.2 U7.3 | length 105.1
  Bottom Layer w10: R33.2@1722.25,1368.05 1723.24,1368.05 1757.1,1334.2 U7.3@1813.3,1334.2
NetR34_1: R34.1 U4.6 | length 99
  Top Layer w10: R34.1@2288.37,602.66 2288.67,602.36 2386.82,602.36 U4.6@2387.1,602.07
NetR47_1: R47.1 R50.2 U8.4 | length 274.6
  Top Layer w10: U8.4@635.03,463.07 635.03,457.16 653.3,438.89 798.48,438.89 819.11,418.27 R50.2@826.61,418.27 ; R50.2@828.26,417.56 R47.1@889.24,417.56
NetR48_1: R48.1 U8.2 | length 98.3
  Top Layer w15: R48.1@656.33,541.94 656.33,535.44 673.83,517.94 677.46,517.94 698.02,497.38 U8.2@698.02,463.07
NetR51_1: R51.1 R52.2 U8.7 | length 122.4
  Top Layer w10: R51.1@697.36,194.62 R51.1@702.25,199.5 ; U8.7@698.02,313.46 698.02,260.31 702.43,255.9 R51.1@702.43,199.77
NetR51_2: R51.2 U8.6 | length 132.4
  Top Layer w10: R51.2@634.55,194.89 635.54,194.89 666.53,225.88 U8.6@666.53,313.46
NetTP4_1: TP4.1 U3.22 | length 347.8
  Top Layer w10: TP4.1@2222.62,1107.22 2368.61,1107.22 2384.93,1090.9 2444.04,1090.9 2460.34,1107.19 2460.34,1155.05 2477.8,1172.51 U3.22@2477.8,1196.54
PICO: J7.4 R22.2 U5.5 | length 660.3
  Top Layer w10: U5.5@1908.96,819.84 1908.96,798.9 1885.43,775.37 1885.43,570.68 J7.4@1962.92,493.2 2016.83,547.11 R22.2@2232.43,547.11
POCI: J7.5 R20.1 R23.2 U4.9 | length 591.4
  Top Layer w10: R20.1@1918.42,680.89 R20.1@1922.48,676.83 ; v1(1926.98,644.81) R20.1@1926.98,681.34 ; J7.5@2041.66,493.2 2052.8,493.2 2075.22,515.61 2170.88,515.61 2316.46,515.61 2337.18,536.34 U4.9@2360.74,536.34
  Bottom Layer w10: v1(1926.98,644.81) 1926.98,596.59 J7.5@2042.91,480.66
R\E\S\E\T\: R10.2 R29.2 U3.16 | length 946.5
  Top Layer w10: R10.2@2277.45,1236.92 2289.78,1249.26 v1(2319.54,1249.26) 2357.68,1249.26 2365.12,1241.82 U3.16@2393.15,1241.82
  Bottom Layer w10: v1(2319.54,1249.26) 2319.54,1141.92 2372.91,1088.55 2423.39,1088.55 2457.16,1122.32 2617.11,1122.32 2630.24,1109.19 2647.69,1109.19 2722.78,1034.1 2877.85,1034.1 2936.45,1092.7 R29.2@2936.45,1094.18
REFOUT: C6.1 U3.13 | length 141
  Top Layer w10: C6.1@2277.31,1350.91 C6.1@2282.41,1350.91 2282.41,1343.41 2287.41,1338.41 2294.91,1338.41 2332.45,1300.87 U3.13@2393.15,1300.87
REFP: C5.1 C21.2 U3.14 U7.5 U7.6 | length 698.2
  Top Layer w10: v1(2013.36,1462.69) 2186.58,1462.69 2252.41,1396.85 2252.41,1315.33 2276.46,1291.28 2277.45,1291.28 2287.54,1281.19 U3.14@2393.15,1281.19
  Bottom Layer w10: C21.2@1957.99,1460.88 1959.79,1462.69 v1(2013.36,1462.69)
  Bottom Layer w20: C21.2@1957.99,1460.88 1957.99,1433.32 1988.5,1402.81 U7.5@1988.5,1359.79 U7.6@1988.5,1334.2
RST: C15.1 J4.1 R25.2 U4.2 | length 655.4
  Top Layer w10: U4.2@2465.84,602.07 2466.11,602.35 2466.11,615.46 2501.01,650.36 2527.69,650.36 2563.63,686.3 R25.2@2563.63,687.29 C15.1@2619.89,687.29 v1(2676.86,687.29)
  Bottom Layer w10: v1(2676.86,687.29) 2730.37,633.78 2730.37,330.68 J4.1@2714.8,315.11
RX: J3.2 R31.1 U4.1 | length 911.6
  Top Layer w10: U4.1@2485.52,602.07 2485.52,608.21 2496.14,618.83 2513.82,618.83 v1(2516.43,621.44)
  Bottom Layer w10: J3.2@1907.36,254.42 1907.36,313.75 R31.1@1912.03,318.42 ; R31.1@1907.36,323.09 1907.36,324.07 1939.04,355.76 2251.52,355.76 2346.97,451.2 2346.97,570.54 2397.87,621.44 v1(2516.43,621.44)
SCLK: J7.3 R21.2 U5.4 | length 742.3
  Top Layer w10: U5.4@1883.96,819.84 1883.96,797.62 1881.09,794.74 1881.09,794.57 1849.44,762.93 1849.44,527.93 J7.3@1884.18,493.2 1937.22,440.16 2118.88,440.16 2159.38,480.66 R21.2@2232.43,480.66
START: R30.2 U3.17 | length 770.3
  Top Layer w10: v1(2346.29,1223.78) 2347.85,1222.21 2393.07,1222.21 U3.17@2393.15,1222.13
  Bottom Layer w10: v1(2346.29,1223.78) 2346.29,1221.33 2336.06,1211.11 2336.06,1146.61 2379.12,1103.55 2412.67,1103.55 2446.44,1137.32 2623.32,1137.32 2636.45,1124.19 2653.9,1124.19 2729,1049.1 2844.69,1049.1 2889.47,1093.88 R30.2@2889.47,1094.87
SWCLK: J4.4 U4.16 | length 153
  Top Layer w10: U4.16@2446.15,451.48 2446.15,347.53 J4.4@2478.58,315.11 ; J4.4@2480.48,317.01 J4.4@2482.72,314.77
SWDIO: J4.5 U4.15 | length 147.7
  Top Layer w10: J4.5@2399.84,315.11 2399.84,319.25 2426.47,345.88 U4.15@2426.47,451.48 ; J4.5@2403.98,314.77 J4.5@2403.98,315.11
TX: J3.1 R32.1 U4.24 | length 832.1
  Top Layer w10: U4.24@2511.6,575.99 2517.75,575.99 2541.22,599.46 2545.75,599.46 v1(2548.36,602.07)
  Bottom Layer w10: J3.1@2007.36,254.42 2007.75,254.81 R32.1@2007.75,312.77 ; R32.1@2007.75,323.09 2240.07,323.09 2361.97,444.99 2361.97,564.33 2391.63,593.99 2536.59,593.99 2544.67,602.07 v1(2548.36,602.07)
USB_D_N: D5.2 J2.2 U4.21 | length 728.1
  Top Layer w10.82: U4.21@2511.6,516.93 2516.92,516.93 2518.86,518.86 2952.63,518.86 2990.84,480.66 2990.84,342.66 2990.84,283.32 2988.66,281.14 J2.2@2988.66,249.33
USB_D_P: D4.2 J2.3 U4.22 | length 758.6
  Top Layer w10.82: U4.22@2511.6,536.62 2516.92,536.62 2518.86,534.69 2959.19,534.69 3006.66,487.21 3006.66,342.66 3006.66,281.84 3007.36,281.14 3007.36,249.33 J2.3@3010.8,245.88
